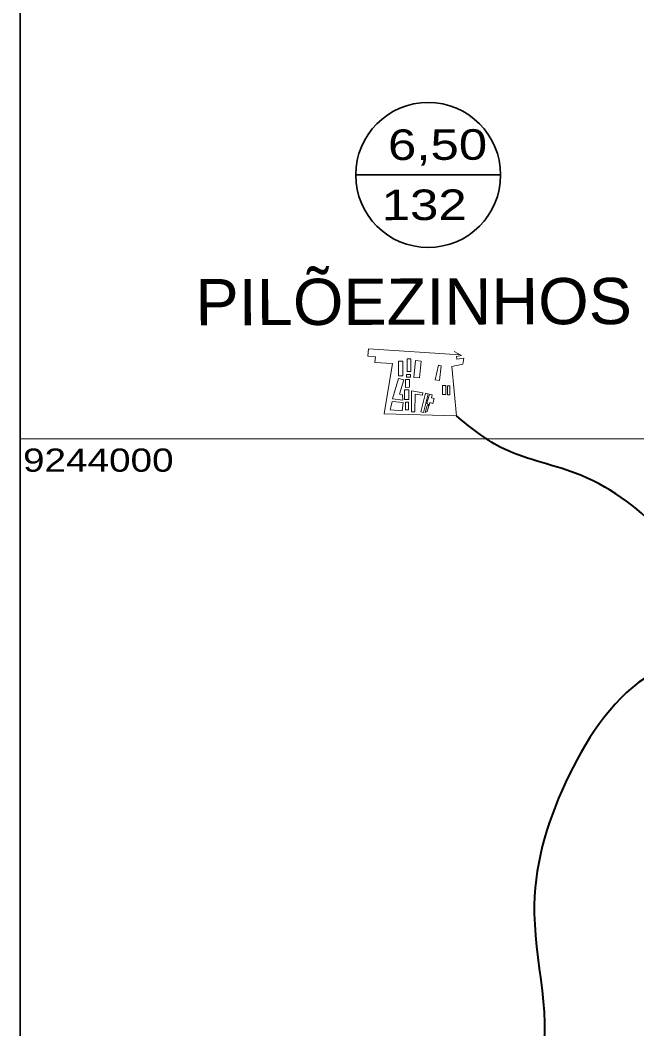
# Model space of a CAD drawing. Extents: x 0 to 1682, y 0 to 1188.
# Drawn here: x 952.3 to 1003.2, y 569.6 to 652.9 of the extents above; entities that cross this region are included whole.
import ezdxf
from ezdxf.enums import TextEntityAlignment as Align

# ---------------------------------------------------------------- set-up
doc = ezdxf.new("R2010")
doc.units = 0
doc.header["$LTSCALE"] = 1.3
doc.linetypes.add('DOT_DASHED', pattern=[7.7, 5, -1.2, 0.3, -1.2])
for name, color, linetype, lineweight in [('1', 7, 'DOT_DASHED', 13), ('6', 7, 'Continuous', 40), ('63', 7, 'Continuous', 25), ('9', 7, 'Continuous', 40)]:
    doc.layers.add(name, color=color, linetype=linetype, lineweight=lineweight)

msp = doc.modelspace()

# ---------------------------------------------------------------- linework, layer by layer
at = {"layer": '1', "linetype": 'Continuous'}
msp.add_lwpolyline([(988.147, 625.493), (988.771, 625.161), (988.349, 625.098), (988.384, 624.869), (988.95, 624.954), (988.872, 624.455), (987.967, 624.253), (988.339, 620.2), (982.374, 620.356), (983.069, 624.499), (981.618, 624.594), (981.649, 625.065), (981.036, 625.105), (981.076, 625.718), (988.656, 625.222)], dxfattribs=at)
for points in [[(983.555, 623.496), (983.552, 624.699), (983.911, 624.7), (983.915, 623.497)], [(984.583, 623.859), (984.58, 624.901), (984.27, 624.9), (984.273, 623.858)], [(984.833, 623.364), (984.953, 624.753), (985.421, 624.713), (985.302, 623.323)], [(986.594, 623.158), (986.876, 624.362), (987.099, 624.31), (986.954, 623.11)], [(983.065, 621.598), (983.568, 623.286), (983.999, 623.158), (983.651, 621.991), (983.889, 621.92), (983.933, 621.489)], [(984.141, 622.543), (984.139, 623.201), (984.461, 623.201), (984.463, 622.544)], [(984.213, 623.387), (984.212, 623.61), (984.559, 623.611), (984.56, 623.388)], [(984.07, 621.551), (984.067, 622.345), (984.414, 622.346), (984.417, 621.552)], [(984.643, 620.511), (984.638, 622.26), (985.581, 622.101), (985.544, 621.884), (984.928, 621.988), (984.916, 620.525)], [(987.193, 621.957), (987.191, 622.701), (987.464, 622.702), (987.466, 621.958)], [(987.615, 621.934), (987.612, 622.678), (987.811, 622.678), (987.813, 621.934)], [(982.918, 620.915), (983.041, 621.375), (983.934, 621.303), (983.878, 620.604), (982.864, 620.685)], [(985.399, 620.514), (985.779, 622.052), (986.001, 621.998), (985.621, 620.459)], [(985.906, 621.247), (986.127, 621.979), (986.353, 621.911), (986.285, 621.685), (986.511, 621.617), (986.389, 621.215), (986.154, 621.286), (986.083, 621.05)], [(984.134, 620.683), (984.132, 621.316), (984.38, 621.317), (984.382, 620.684)], [(985.759, 620.477), (985.931, 621.048), (986.065, 621.008), (985.925, 620.545)]]:
    msp.add_lwpolyline(points, close=True, dxfattribs=at)
at = {"layer": '6'}
for points in [[(1007.819, 607.104), (1005.163, 610.631), (998.165, 615.452), (991.956, 617.614), (988.339, 620.2)], [(1016.97, 601.589), (1003.954, 598.568), (997.364, 589.92), (994.779, 579.078), (994.779, 565.267), (988.706, 558.168), (983.925, 548.616), (978.11, 542.421)]]:
    msp.add_spline(points, degree=3, dxfattribs=at)
at = {"layer": '63', "lineweight": 13}
msp.add_line((1640.404, 618.279), (952.314, 618.279), dxfattribs=at)
at = {"layer": '63', "lineweight": 35}
msp.add_lwpolyline([(1640.404, 427.142), (952.314, 427.142), (952.314, 783.93)], dxfattribs=at)
at = {"layer": '9', "lineweight": 35}
msp.add_line((980.029, 640.082), (992, 640.082), dxfattribs=at)
msp.add_circle((986.014, 640.082), 5.985, dxfattribs=at)

# ---------------------------------------------------------------- texts
at = {"layer": '63', "width": 1.25}
msp.add_text('9244000', height=1.911, dxfattribs=at).set_placement((952.549, 615.576))
at = {"layer": '9', "width": 1.25}
for s, p in [('6,50 ', (987.376, 641.328)), ('132', (985.685, 636.355))]:
    msp.add_text(s, height=2.52, rotation=0.17, dxfattribs=at).set_placement(p, align=Align.CENTER)
at = {"layer": '9', "width": 1.05}
msp.add_text('PILÕEZINHOS', height=3.819, rotation=0.17, dxfattribs=at).set_placement((966.797, 627.661))

doc.saveas('drawing.dxf')
